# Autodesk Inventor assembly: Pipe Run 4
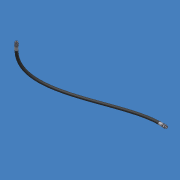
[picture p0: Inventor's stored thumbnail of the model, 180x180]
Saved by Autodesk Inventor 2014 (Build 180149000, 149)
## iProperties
Company: Autodesk, Inc.
Created: 2004-07
Part Number: Pipe Run 4
Document SubType Name: Tube & Pipe
Designer: Autodesk, Inc.
Manufacturer: Standard
Standards Organization: Custom
Mass: 507.426 g
Surface Area: 1513.46 cm^2
Volume: 335.879 cm^3
Density: 1.51074 g/cm^3
TPVersion: 11.0.2
Author: Autodesk, Inc.
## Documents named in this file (2)
- C:\Users\iTools\Desktop\tutorial files\Tube and Pipe\Accumulator\AIP\Hose Run1\Hose Run1.iam
- C:\Users\iTools\Desktop\tutorial files\Tube and Pipe\Accumulator\AIP\Hose Run1\pifhose.1110965117912.iam
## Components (1 placed, 1 different names)
1. Flexible Hose 2 [sub-assembly]
